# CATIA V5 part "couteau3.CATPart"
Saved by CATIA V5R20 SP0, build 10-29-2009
Part number: couteau3
Bounding box of the stored display mesh (mm): x 3 to 7, y -89.999 to 2.319, z 30.001 to 86.579
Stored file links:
  D:\Dropbox\IAO_2012\IAO_2012_991_jambrosino\IAO_2012_991_jambrosino_Catia\Assemblage\couteau3.CATPart
  D:\Dropbox\IAO_2012\IAO_2012_991_jambrosino\IAO_2012_991_jambrosino_Catia\Assemblage\Ass_IAO_991_skl.CATProduct
  D:\Dropbox\IAO_2012\IAO_2012_991_jambrosino\IAO_2012_991_jambrosino_Catia\Assemblage\bati.CATPart
  J:\IAO_Mecanisme_991\IAO_Mecanisme_991_CATIA\skl_bielle_7.CATPart
  J:\IAO_Mecanisme_991\IAO_Mecanisme_991_CATIA\skl_couteau_3.CATPart
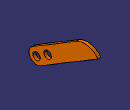
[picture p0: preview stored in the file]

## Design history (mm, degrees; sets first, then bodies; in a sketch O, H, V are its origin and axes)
Set1
  Plane1: linked copy from another document
  DatumPoint1: linked copy from another document
  DatumPoint2: linked copy from another document
  Line1: linked copy from another document
Body1 (main body)
  Sketch1 on Plane1, origin (3, 0, 0), H (0, -1, 0), V (0, 0, 1)
    point P1 (80, 40)
    line L1 (27.1447, 83.3751) -> (85.145, 48.5749)
    arc A1 centre (80, 40) radius 10 from (85.145, 48.5749) to (74.855, 31.4251) cw
    point P3 (27.1447, 83.3751)
    circle A2 centre (65, 49) radius 5
    point P5 (65, 49)
    circle A3 centre (80, 40) radius 5
    axis line L2 (109.371, 41.5815) -> (-20.629, 41.5815)
    reference projected point E1 (80, 40) from vertex of DatumPoint1
    reference projected point E2 (65, 49) from DatumPoint2
    reference projected line E3 (65, 49) -> (28.5504, 70.8697) from Line1
    line L3 (74.855, 31.4251) -> (-2.3193, 77.7297)
    point P8 (-2.3193, 77.7297)
    reference projected line E4 (65, 49) -> (28.5504, 70.8697) from Line1
    arc A4 centre (15.5686, 64.0815) radius 22.5 from (27.1447, 83.3751) to (-2.3193, 77.7297) ccw
    point P10 (-2.3193, 77.7297)
    point P11 (27.1447, 83.3751)
    radius A3 = 5
    radius A2 = 5
    radius A1 = 10
    radius A4 = 22.5
    length L3 = 90
    tangency: A1 L1, A1 L3, A4 L2, L1 A4
    horizontal: L2 H
    coincidence: P1 E1, P5 E2, P10 L3, P10 P8, P3 P11
    parallelism: L1 E3, L3 L1, L3 E4
  Pad1: profile Sketch1, direction (1, 0, 0), length 4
